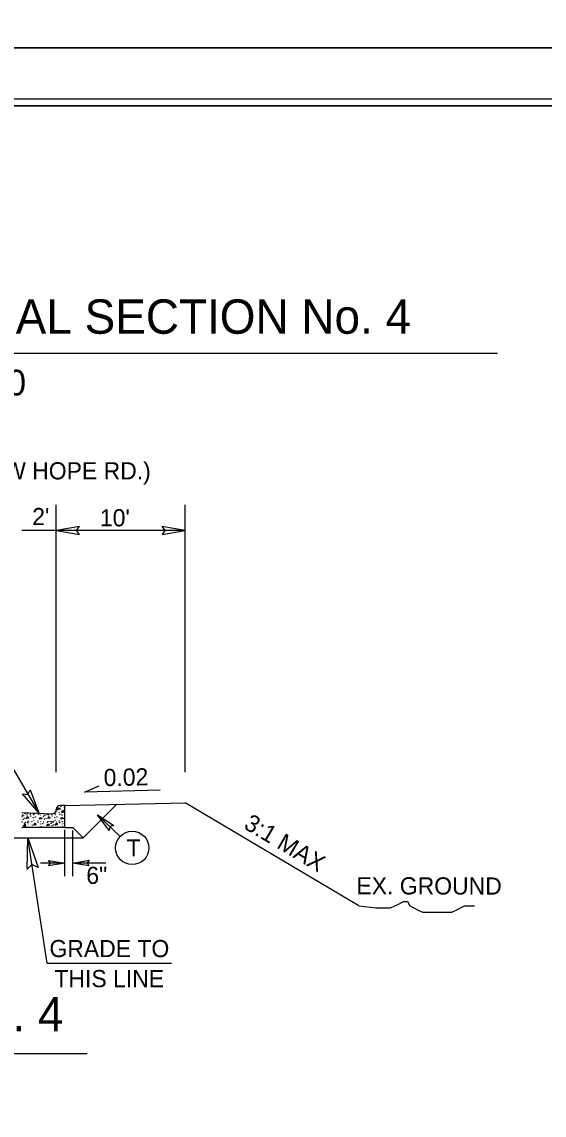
# Model space of a CAD drawing. Extents: x 2320980 to 2456309, y 595047 to 606177.
# Drawn here: x 2455839.2 to 2455879.6, y 596658.9 to 596743.6 of the extents above; entities that cross this region are included whole.
import ezdxf

# ---------------------------------------------------------------- set-up
doc = ezdxf.new("R2010")
doc.units = 0
for name, color, linetype in [('Old_Level_1', 7, 'Continuous'), ('Old_Level_11', 7, 'Continuous'), ('Old_Level_2', 7, 'Continuous'), ('Old_Level_20', 7, 'Continuous'), ('Old_Level_21', 7, 'Continuous'), ('Old_Level_3', 7, 'Continuous'), ('Prop Dimension Text', 7, 'Continuous'), ('Sheet Plan CELL', 7, 'Continuous'), ('Sheet Plot Border Inside CELL', 7, 'Continuous'), ('Sheet Plot Border Outside CELL', 7, 'Continuous'), ('Typical Berm CELL', 7, 'Continuous'), ('Typical Curb CELL', 7, 'Continuous'), ('Typical Hinge Slope Arterial CELL', 7, 'Continuous'), ('Typical ID Circle CELL', 7, 'Continuous'), ('Typical Pavement Slope CELL', 7, 'Continuous'), ('Typical Terminator CELL', 7, 'Continuous')]:
    doc.layers.add(name, color=color, linetype=linetype)

msp = doc.modelspace()

# ---------------------------------------------------------------- linework, layer by layer
at = {"layer": 'Old_Level_11'}
msp.add_lwpolyline([(2455839.592, 596677.929), (2455839.631, 596680.358), (2455840.423, 596678.045), (2455839.955, 596678.282)], close=True, dxfattribs=at)
at = {"layer": 'Old_Level_21'}
for p, q in [((2455841.83, 596685.453), (2455841.83, 596706.155)), ((2455851.83, 596685.453), (2455851.83, 596706.155)), ((2455851.83, 596704.164), (2455839.17, 596704.164)), ((2455865.293, 596675.089), (2455851.83, 596683.063)), ((2455842.495, 596677.384), (2455842.495, 596680.975)), ((2455843.128, 596677.384), (2455843.128, 596680.928)), ((2455841.145, 596670.644), (2455839.631, 596680.358)), ((2455841.145, 596670.644), (2455850.764, 596670.644))]:
    msp.add_line(p, q, dxfattribs=at)
at = {"layer": 'Old_Level_3'}
for p, q in [((2455768.034, 596717.911), (2455876.035, 596717.911)), ((2455799.311, 596663.653), (2455844.231, 596663.653))]:
    msp.add_line(p, q, dxfattribs=at)
at = {"layer": 'Prop Dimension Text'}
for p, q in [((2455846.794, 596680.468), (2455845.036, 596682.149)), ((2455842.495, 596678.397), (2455840.608, 596678.397)), ((2455845.69, 596678.397), (2455843.128, 596678.397))]:
    msp.add_line(p, q, dxfattribs=at)
msp.add_lwpolyline([(2455849.893, 596684.055), (2455844.037, 596683.894), (2455845.174, 596684.383)], dxfattribs=at)
msp.add_circle((2455847.729, 596679.574), 1.293, dxfattribs=at)
at = {"layer": 'Sheet Plan CELL'}
for points in [[(2455742.104, 596527.076), (2455742.099, 596737.071), (2456002.097, 596737.079), (2456002.099, 596707.066), (2456042.107, 596707.064), (2456042.107, 596527.076)], [(2456042.112, 596737.076), (2455742.104, 596737.076), (2455742.104, 596527.076), (2456042.107, 596527.076)]]:
    msp.add_lwpolyline(points, close=True, dxfattribs=at)
at = {"layer": 'Sheet Plot Border Inside CELL'}
msp.add_lwpolyline([(2455711.407, 596526.574), (2456044.604, 596526.576), (2456044.607, 596737.574), (2455711.407, 596737.574)], close=True, dxfattribs=at)
at = {"layer": 'Sheet Plot Border Outside CELL'}
for points in [[(2455708.807, 596741.574), (2456045.507, 596741.574), (2456045.507, 596960.574), (2455708.807, 596960.574)], [(2455708.807, 596522.574), (2456045.507, 596522.574), (2456045.507, 596741.574), (2455708.807, 596741.574)]]:
    msp.add_lwpolyline(points, close=True, dxfattribs=at)
at = {"layer": 'Typical Berm CELL'}
for p, q in [((2455842.495, 596682.869), (2455851.83, 596683.063)), ((2455842.495, 596681.152), (2455843.118, 596681.152))]:
    msp.add_line(p, q, dxfattribs=at)
at = {"layer": 'Typical Curb CELL'}
for p, q in [((2455839.17, 596682.314), (2455841.498, 596682.218)), ((2455841.83, 596682.536), (2455841.83, 596682.55)), ((2455841.944, 596682.516), (2455842.027, 596682.669)), ((2455842.164, 596682.569), (2455841.944, 596682.516)), ((2455842.027, 596682.669), (2455842.164, 596682.569)), ((2455842.495, 596682.869), (2455842.148, 596682.869)), ((2455842.241, 596682.425), (2455842.263, 596682.305)), ((2455842.446, 596682.366), (2455842.241, 596682.425)), ((2455842.263, 596682.305), (2455842.446, 596682.366)), ((2455842.495, 596681.152), (2455842.495, 596682.869)), ((2455839.305, 596681.256), (2455839.42, 596681.416)), ((2455839.42, 596681.416), (2455839.466, 596681.265)), ((2455839.516, 596681.857), (2455839.631, 596682.017)), ((2455839.677, 596681.866), (2455839.516, 596681.857)), ((2455839.631, 596682.017), (2455839.677, 596681.866)), ((2455840.094, 596681.348), (2455840.209, 596681.507)), ((2455840.209, 596681.507), (2455840.255, 596681.356)), ((2455840.535, 596681.789), (2455840.618, 596681.942)), ((2455840.755, 596681.842), (2455840.535, 596681.789)), ((2455840.618, 596681.942), (2455840.755, 596681.842)), ((2455841.112, 596681.28), (2455841.195, 596681.432)), ((2455841.179, 596681.857), (2455841.292, 596682.017)), ((2455841.338, 596681.866), (2455841.179, 596681.857)), ((2455841.195, 596681.432), (2455841.333, 596681.333)), ((2455841.292, 596682.017), (2455841.338, 596681.866)), ((2455841.756, 596681.348), (2455841.87, 596681.507)), ((2455841.87, 596681.507), (2455841.916, 596681.356)), ((2455842.195, 596681.789), (2455842.279, 596681.942)), ((2455842.416, 596681.842), (2455842.195, 596681.789)), ((2455842.279, 596681.942), (2455842.416, 596681.842)), ((2455842.495, 596681.152), (2455839.17, 596681.152)), ((2455839.466, 596681.265), (2455839.305, 596681.256)), ((2455840.255, 596681.356), (2455840.094, 596681.348)), ((2455841.333, 596681.333), (2455841.112, 596681.28)), ((2455841.916, 596681.356), (2455841.756, 596681.348))]:
    msp.add_line(p, q, dxfattribs=at)
for centre in [(2455839.434, 596682.236), (2455839.623, 596682.259), (2455841.902, 596682.395), (2455842.062, 596682.328), (2455842.188, 596682.768), (2455842.409, 596682.479), (2455842.477, 596682.722), (2455839.184, 596681.577), (2455839.192, 596681.987), (2455839.215, 596682.116), (2455839.268, 596681.797), (2455839.289, 596682.071), (2455839.388, 596681.478), (2455839.396, 596681.858), (2455839.464, 596681.547), (2455839.563, 596682.123), (2455839.624, 596681.561), (2455839.647, 596681.439), (2455839.677, 596681.638), (2455839.821, 596682.176), (2455839.859, 596682.04), (2455839.95, 596681.607), (2455840.056, 596681.926), (2455840.094, 596682.154), (2455840.102, 596681.721), (2455840.117, 596682.221), (2455840.178, 596681.569), (2455840.223, 596681.964), (2455840.413, 596681.653), (2455840.437, 596681.531), (2455840.459, 596682.183), (2455840.618, 596682.116), (2455840.634, 596681.417), (2455840.641, 596681.6), (2455840.801, 596681.455), (2455840.846, 596681.577), (2455840.853, 596681.987), (2455840.876, 596682.116), (2455840.929, 596681.797), (2455840.951, 596682.071), (2455841.057, 596681.858), (2455841.095, 596682.181), (2455841.125, 596681.547), (2455841.196, 596681.607), (2455841.224, 596682.123), (2455841.338, 596681.638), (2455841.431, 596681.478), (2455841.454, 596681.607), (2455841.482, 596682.176), (2455841.52, 596682.04), (2455841.528, 596681.561), (2455841.611, 596681.607), (2455841.718, 596681.926), (2455841.756, 596682.154), (2455841.763, 596681.721), (2455841.778, 596682.221), (2455841.839, 596681.569), (2455841.885, 596681.964), (2455842.074, 596681.653), (2455842.098, 596681.531), (2455842.12, 596682.183), (2455842.279, 596682.116), (2455842.295, 596681.417), (2455842.302, 596681.6), (2455842.462, 596681.455), (2455839.974, 596681.349), (2455840.679, 596681.212), (2455841.507, 596681.288), (2455841.635, 596681.349), (2455842.341, 596681.212)]:
    msp.add_circle(centre, 0.0107, dxfattribs=at)
for centre, start, end in [((2455841.511, 596682.536), 267.61554, 360), ((2455842.148, 596682.55), 90, 180)]:
    msp.add_arc(centre, 0.319, start, end, dxfattribs=at)
at = {"layer": 'Typical Hinge Slope Arterial CELL'}
msp.add_lwpolyline([(2455865.293, 596675.089), (2455866.604, 596674.926), (2455866.932, 596674.926), (2455867.424, 596674.926), (2455867.752, 596674.926), (2455868.079, 596675.089), (2455868.407, 596675.253), (2455868.735, 596675.418), (2455869.062, 596675.418), (2455869.227, 596675.089), (2455869.554, 596674.926), (2455869.882, 596674.761), (2455870.21, 596674.598), (2455870.537, 596674.598), (2455870.865, 596674.598), (2455871.193, 596674.598), (2455871.52, 596674.598), (2455871.848, 596674.598), (2455872.176, 596674.598), (2455872.503, 596674.598), (2455872.831, 596674.761), (2455873.159, 596674.926), (2455873.486, 596675.089), (2455873.979, 596675.089), (2455874.25, 596675.089)], dxfattribs=at)
at = {"layer": 'Typical ID Circle CELL'}
msp.add_line((2455838.26, 596686.098), (2455840.485, 596682.281), dxfattribs=at)
at = {"layer": 'Typical Pavement Slope CELL'}
for p in [(2455846.536, 596682.953), (2455843.118, 596681.152), (2455832.664, 596680.382)]:
    msp.add_line(p, (2455843.926, 596680.343), dxfattribs=at)
at = {"layer": 'Typical Terminator CELL'}
for points in [[(2455843.626, 596704.473), (2455841.83, 596704.164), (2455843.636, 596703.844), (2455843.406, 596704.164)], [(2455850.035, 596703.854), (2455851.83, 596704.164), (2455850.025, 596704.483), (2455850.254, 596704.164)], [(2455839.812, 596684.083), (2455840.485, 596682.281), (2455839.234, 596683.758), (2455839.647, 596683.719)], [(2455845.939, 596680.928), (2455845.036, 596682.149), (2455846.307, 596681.301), (2455845.985, 596681.241)], [(2455841.248, 596678.611), (2455842.495, 596678.397), (2455841.241, 596678.175), (2455841.4, 596678.397)], [(2455844.374, 596678.182), (2455843.128, 596678.397), (2455844.381, 596678.618), (2455844.222, 596678.397)]]:
    msp.add_lwpolyline(points, close=True, dxfattribs=at)

# ---------------------------------------------------------------- texts
at = {"layer": 'Old_Level_1'}
msp.add_text('EX. GROUND', height=1.33, rotation=359.91026, dxfattribs=at).set_placement((2455865.098, 596675.974))
at = {"layer": 'Old_Level_2'}
for s, height, p in [('TRANSITION FROM EXISTING TO TYPICAL SECTION No. 4', 2.66, (2455770.713, 596719.41)), ('-Y1- STA. 10+45.00 TO 12+55.00', 1.995, (2455799.453, 596714.627)), ('TYPICAL SECTION No. 4', 2.66, (2455801.282, 596665.352))]:
    msp.add_text(s, height=height, dxfattribs=at).set_placement(p)
at = {"layer": 'Old_Level_20'}
msp.add_text('T', height=1.33, dxfattribs=at).set_placement((2455847.291, 596678.909))
at = {"layer": 'Old_Level_21'}
for s, p in [('-Y1- SR 1003 (NEW HOPE RD.)', (2455823.469, 596708.126)), ("10'", (2455845.222, 596704.487)), ('6"', (2455844.167, 596676.786)), ('GRADE TO', (2455841.309, 596671.111)), ('THIS LINE', (2455841.696, 596668.783))]:
    msp.add_text(s, height=1.33, dxfattribs=at).set_placement(p)
for s, rotation, p in [("2'", 0.00016, (2455839.975, 596704.581)), ('0.02', 1.14561, (2455845.522, 596684.355)), ('3:1 MAX', 329.36161, (2455856.287, 596681.133))]:
    msp.add_text(s, height=1.33, rotation=rotation, dxfattribs=at).set_placement(p)

doc.saveas('drawing.dxf')
